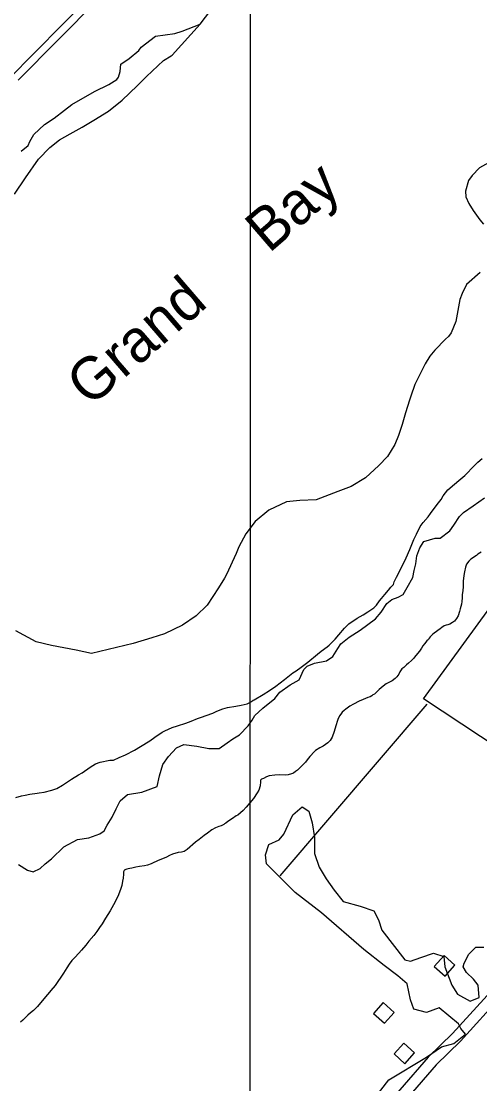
# Model space of a CAD drawing. Extents: x 3263578 to 3301413, y 764927 to 798602.
# Drawn here: x 3274964 to 3276220, y 776528 to 779438 of the extents above; entities that cross this region are included whole.
import ezdxf

# ---------------------------------------------------------------- set-up
doc = ezdxf.new("R2010")
doc.units = 0
for name, color, linetype in [('V-BLDG-OTLN', 7, 'Continuous'), ('V-GRID-MAJR', 7, 'Continuous'), ('V-RIVR-IDEN', 7, 'Continuous'), ('V-ROAD-CNTR', 7, 'Continuous'), ('V-SITE-VEGE', 7, 'Continuous'), ('V-TOPO-SHOR', 7, 'Continuous')]:
    doc.layers.add(name, color=color, linetype=linetype)

msp = doc.modelspace()

# ---------------------------------------------------------------- linework, layer by layer
at = {"layer": 'V-BLDG-OTLN'}
for points in [[(3276125.3, 776822.8), (3276151.9, 776852.7), (3276122.1, 776879.3), (3276095.4, 776849.5)], [(3275958.7, 776693.9), (3275985.3, 776723.7), (3275955.5, 776750.4), (3275928.8, 776720.5)], [(3276014.8, 776583.3), (3276041.5, 776613.1), (3276011.6, 776639.8), (3275985, 776609.9)]]:
    msp.add_lwpolyline(points, close=True, dxfattribs=at)
at = {"layer": 'V-GRID-MAJR'}
msp.add_spline([(3275591.3, 775830), (3275592.2, 781889.4), (3275593.1, 787951.5), (3275593.9, 794013.5), (3275593.9, 794016.1)], degree=3, dxfattribs=at)
at = {"layer": 'V-ROAD-CNTR'}
for points in [[(3274955.7, 779276.4), (3275392.6, 779717.5), (3275797.9, 780131.6), (3276038.2, 780379.7)], [(3277194.8, 777970.7), (3277056, 777784.8), (3276935.6, 777620.8), (3276845.7, 777486), (3276773.8, 777392.2), (3276625.5, 777218), (3276480.6, 777046.5), (3276328.4, 776869.2), (3276259.2, 776790.9), (3276145.3, 776665.7), (3276078.7, 776600.9), (3276001.2, 776511.3), (3275907.5, 776403.5), (3275821.9, 776296.9), (3275728.7, 776181.5), (3275680.8, 776116.1), (3275632.5, 776068.6), (3275515.4, 775977.6), (3275428.3, 775913), (3275327.1, 775831.8)], [(3277218.8, 777952.7), (3277080.1, 777766.9), (3276960.2, 777603.6), (3276870.1, 777468.6), (3276797.2, 777373.4), (3276648.4, 777198.6), (3276503.4, 777027.1), (3276351, 776849.5), (3276281.5, 776770.9), (3276166.9, 776644.8), (3276100.5, 776580.2), (3276023.8, 776491.6), (3275930.5, 776384.3), (3275845.3, 776278.1), (3275752.5, 776163.2), (3275703.5, 776096.4), (3275652.3, 776046), (3275533.6, 775953.7), (3275446.6, 775889.2), (3275376.6, 775833.1)]]:
    msp.add_lwpolyline(points, dxfattribs=at)
at = {"layer": 'V-SITE-VEGE'}
for p, q in [((3275683, 777211.9), (3275708, 777265.1)), ((3275708, 777265.1), (3275733.1, 777287)), ((3275733.1, 777287), (3275751.8, 777274.5)), ((3275751.8, 777274.5), (3275761.2, 777243.2)), ((3275761.2, 777243.2), (3275767.5, 777202.5)), ((3275670.5, 777196.2), (3275683, 777211.9)), ((3275767.5, 777202.5), (3275767.5, 777158.7)), ((3275632.9, 777155.5), (3275642.3, 777183.7)), ((3275642.3, 777183.7), (3275670.5, 777196.2)), ((3275636, 777130.5), (3275632.9, 777155.5)), ((3275767.5, 777158.7), (3275780, 777121.1)), ((3275714.3, 777052.2), (3275636, 777130.5)), ((3275780, 777121.1), (3275798.8, 777089.8)), ((3275798.8, 777089.8), (3275820.7, 777058.5)), ((3275820.7, 777058.5), (3275845.7, 777027.2)), ((3275786.3, 776995.9), (3275714.3, 777052.2)), ((3275845.7, 777027.2), (3275892.6, 777014.7)), ((3275892.6, 777014.7), (3275930.2, 777002.1)), ((3275930.2, 777002.1), (3275942.7, 776977.1)), ((3275902, 776895.7), (3275786.3, 776995.9)), ((3275942.7, 776977.1), (3275952.1, 776948.9)), ((3275952.1, 776948.9), (3276014.7, 776867.5)), ((3275958.4, 776851.9), (3275902, 776895.7)), ((3276058.5, 776873.8), (3276092.9, 776886.3)), ((3276092.9, 776886.3), (3276121.1, 776876.9)), ((3276177.4, 776858.1), (3276189.9, 776883.2)), ((3276189.9, 776883.2), (3276208.7, 776901.9)), ((3276208.7, 776901.9), (3276230.6, 776901.9)), ((3276014.7, 776867.5), (3276030.3, 776864.4)), ((3276030.3, 776864.4), (3276058.5, 776873.8)), ((3276121.1, 776876.9), (3276124.2, 776848.7)), ((3276174.3, 776848.7), (3276177.4, 776858.1)), ((3275995.9, 776823.7), (3275958.4, 776851.9)), ((3276020.9, 776801.8), (3275995.9, 776823.7)), ((3276124.2, 776848.7), (3276143, 776798.6)), ((3276183.7, 776833.1), (3276174.3, 776848.7)), ((3276202.4, 776814.3), (3276183.7, 776833.1)), ((3276030.3, 776757.9), (3276020.9, 776801.8)), ((3276143, 776798.6), (3276158.6, 776773.6)), ((3276215, 776798.6), (3276202.4, 776814.3)), ((3276218.1, 776764.2), (3276215, 776798.6)), ((3276158.6, 776773.6), (3276193.1, 776754.8)), ((3276039.7, 776732.9), (3276030.3, 776757.9)), ((3276108.6, 776736), (3276074.1, 776723.5)), ((3276161.8, 776692.2), (3276108.6, 776736)), ((3276193.1, 776754.8), (3276218.1, 776764.2)), ((3276074.1, 776723.5), (3276039.7, 776732.9)), ((3276168, 776679.7), (3276161.8, 776692.2)), ((3276180.5, 776664), (3276168, 776679.7)), ((3276149.2, 776639), (3276180.5, 776664)), ((3276074.1, 776601.4), (3276114.8, 776629.6)), ((3276114.8, 776629.6), (3276149.2, 776639)), ((3275970.9, 776538.8), (3276074.1, 776601.4)), ((3275870.7, 776410.4), (3275970.9, 776538.8))]:
    msp.add_line(p, q, dxfattribs=at)
for points in [[(3275429.3, 777521.1), (3275447.1, 777528.9), (3275457.9, 777532.4), (3275470.8, 777536.5), (3275489.1, 777543.2), (3275499.9, 777548.4), (3275516, 777555.1), (3275528.9, 777558.2), (3275551.5, 777562.1), (3275566.5, 777564.6), (3275582.6, 777568.6), (3275586.4, 777570.2), (3275594.5, 777575.4), (3275598.9, 777578.6), (3275602.1, 777579.6), (3275626.4, 777594.2), (3275643.7, 777605.2), (3275661, 777616.7), (3275684.9, 777635.1), (3275708.2, 777653.5), (3275716.8, 777659.3), (3275730.9, 777669.3), (3275748.8, 777682.9), (3275775.9, 777704.5), (3275785.6, 777712.4), (3275801.9, 777725), (3275807.8, 777729.7), (3275823.6, 777745.5), (3275833.9, 777757.2), (3275849.8, 777775.7), (3275861.7, 777787.3), (3275883.9, 777803), (3275900.6, 777812.4), (3275913.6, 777820.3), (3275929.8, 777831.3), (3275937.5, 777839.2), (3275945.1, 777850.9), (3275950.6, 777857.2), (3275959.8, 777868.3), (3275970.2, 777879.9), (3275976.7, 777887.9), (3275980, 777891.6), (3275983.3, 777895.8), (3275985.5, 777902.7), (3275991.6, 777915.5), (3276013.7, 777958), (3276018.1, 777968.7), (3276028.1, 777991), (3276039.7, 778018.2), (3276046.9, 778033.6), (3276056.9, 778053.8), (3276065.1, 778065.5), (3276078.1, 778080.8), (3276084.7, 778089.8), (3276103.3, 778114.2), (3276113.7, 778128.5), (3276119.7, 778138), (3276125.7, 778146.5), (3276132.3, 778155), (3276150.2, 778170.2), (3276162.1, 778180.2), (3276178.9, 778193.9), (3276188.1, 778202.9), (3276196.3, 778211.9), (3276207.2, 778223.5), (3276214.8, 778230.3), (3276226.2, 778240.3)], [(3276223.5, 777983.8), (3276214.8, 777978.1), (3276210.5, 777974.9), (3276195.3, 777964.4), (3276189.9, 777959.2), (3276183.3, 777950.7), (3276180.5, 777943.2), (3276177.7, 777929.9), (3276175.9, 777919.7), (3276174.6, 777904.2), (3276174.4, 777889.2), (3276173.2, 777879.1), (3276171.9, 777866.8), (3276171.8, 777859.3), (3276171.1, 777848.6), (3276169.4, 777841.1), (3276166, 777828.8), (3276164.3, 777821.4), (3276160.4, 777809.6), (3276156.5, 777802.7), (3276150.5, 777795.3), (3276145.6, 777791.7), (3276138.1, 777786.9), (3276132.1, 777784.9), (3276127.8, 777783.9), (3276125.1, 777782.9), (3276121.9, 777781.8), (3276116, 777777.6), (3276111.1, 777774), (3276105.1, 777769.8), (3276101.3, 777766.6), (3276095.4, 777761.9), (3276090.5, 777758.7), (3276088.9, 777757.1), (3276084, 777751.9), (3276081.2, 777748.2), (3276079.1, 777744.4), (3276074.7, 777740.8), (3276068.7, 777733.3), (3276064.3, 777727), (3276060.5, 777721.1), (3276054.5, 777712.7), (3276049.6, 777706.3), (3276041.4, 777696.8), (3276039.2, 777693.6), (3276032.7, 777687.3), (3276024.5, 777679.9), (3276019.6, 777675.2), (3276012, 777668.3), (3276006.6, 777664.1), (3276001.2, 777656.1), (3275997.9, 777650.3), (3275992.9, 777642.3), (3275988.6, 777637.6), (3275980.4, 777631.3), (3275976.1, 777629.7), (3275963.2, 777623), (3275955.1, 777617.2), (3275944.7, 777608.2), (3275931.2, 777595.1), (3275927.4, 777593), (3275924.7, 777590.9), (3275919.8, 777587.7), (3275913.3, 777585.7), (3275900.4, 777580.5), (3275889.6, 777575.9), (3275874, 777568.1), (3275864.3, 777562.3), (3275853.4, 777554.4), (3275848.6, 777550.2), (3275842.6, 777546), (3275839.3, 777540.2), (3275836, 777535.9), (3275831.1, 777525.8), (3275829.9, 777522.6), (3275826, 777508.2), (3275821.5, 777492.8), (3275815.9, 777477.3), (3275810.4, 777468.3), (3275803.9, 777461.4), (3275791.4, 777453.1), (3275782.2, 777448.4), (3275770.3, 777440.5), (3275764.4, 777435.8), (3275757.3, 777427.3), (3275754.6, 777424.7), (3275747.5, 777415.1), (3275742.6, 777408.8)], [(3274949.5, 777311.8), (3274964.6, 777316.4), (3274975.3, 777318.9), (3274987.7, 777321.4), (3275007.6, 777324.3), (3275012.9, 777324.8), (3275026.9, 777326.7), (3275048.4, 777332.3), (3275061.3, 777336.4), (3275077, 777345.8), (3275101.9, 777362.6), (3275121.3, 777374.1), (3275131, 777379.3), (3275153.2, 777395.6), (3275167.8, 777403.9), (3275180.7, 777408.5), (3275207.1, 777414), (3275217.2, 777414.4), (3275232.3, 777421.7), (3275249.6, 777428.9), (3275274.4, 777442), (3275291.2, 777451.4), (3275316, 777467.1), (3275330.1, 777477), (3275350.1, 777490.7), (3275357.1, 777494.3), (3275377.6, 777503.6), (3275392.2, 777508.2), (3275415.3, 777515.4), (3275429.3, 777521.1)], [(3275742.6, 777408.8), (3275733.9, 777399.8), (3275720.8, 777387.2), (3275715.4, 777383), (3275709.4, 777378.8), (3275704.6, 777377.2), (3275695.4, 777374.1), (3275686.9, 777373.7), (3275670.3, 777374), (3275658.5, 777373.6), (3275642.9, 777371.2), (3275635.9, 777368.6), (3275627.3, 777364.4), (3275622.4, 777362.4), (3275619.7, 777359.2), (3275619.1, 777355.5), (3275618.9, 777343.7), (3275615, 777332.5), (3275610.1, 777324.5), (3275600.2, 777309.1), (3275580.6, 777285.9), (3275571.9, 777276.4), (3275557.8, 777264.2), (3275552.9, 777261.6), (3275543.2, 777254.8), (3275530.2, 777246.4), (3275524.2, 777241.7), (3275521, 777239.6), (3275518.8, 777238.6), (3275515.1, 777236), (3275511.8, 777234.4), (3275505.4, 777232.3), (3275496.2, 777228.7), (3275486.5, 777223.5), (3275474.6, 777214.6), (3275465.4, 777208.3), (3275451.3, 777197.3), (3275441.5, 777189.4), (3275418.7, 777169.9), (3275410.1, 777164.7), (3275403.1, 777162.6), (3275394, 777161.2), (3275378.9, 777156.6), (3275369.8, 777152.9), (3275361.7, 777148.8), (3275350.9, 777144.1), (3275343.9, 777141.6), (3275337.4, 777139), (3275323.9, 777132.2), (3275320.1, 777130.1), (3275309.9, 777126.5), (3275301.9, 777125), (3275287.9, 777123.1), (3275278.2, 777121.6), (3275267, 777119.1), (3275261.6, 777118.1), (3275256.7, 777116.6), (3275253, 777115.6), (3275250.3, 777115.1), (3275248.1, 777114), (3275247, 777112.5), (3275246, 777112.5), (3275244.3, 777108.7), (3275244.2, 777102.3), (3275243, 777091.1), (3275241.8, 777083.1), (3275239.5, 777071.3), (3275237.2, 777063.3), (3275230.5, 777045.2), (3275223.9, 777031.9), (3275217.3, 777018.1), (3275207.9, 777002.2), (3275195.3, 776982), (3275186, 776966.1), (3275178.8, 776956), (3275171.7, 776944.9), (3275163.5, 776934.3), (3275149.4, 776918.4), (3275141.2, 776907.8), (3275129.2, 776894.1), (3275122.1, 776886.1), (3275110.7, 776874), (3275102.5, 776865.6), (3275095.4, 776855.5), (3275088.8, 776845.9), (3275080.1, 776831.1), (3275057.1, 776797.7), (3275045.1, 776783.9), (3275041.8, 776779.2), (3275030.9, 776766.5), (3275009.1, 776740), (3274997.7, 776728.9), (3274989.5, 776722.1), (3274982.5, 776715.8), (3274968.4, 776702), (3274961.8, 776696.8)]]:
    msp.add_lwpolyline(points, dxfattribs=at)
at = {"layer": 'V-TOPO-SHOR'}
for p, q in [((3274928.5, 779278.1), (3275184.5, 779538.4)), ((3276075.3, 777567.7), (3275672.7, 777098.1))]:
    msp.add_line(p, q, dxfattribs=at)
for points in [[(3274946, 778964.2), (3274975.6, 779008.5), (3275011.4, 779059.8), (3275042.6, 779091.8), (3275069.3, 779113.3), (3275098.5, 779129.6), (3275131.2, 779147.5), (3275163.1, 779167.2), (3275202.9, 779191.2), (3275240.2, 779221.3), (3275282, 779261.1), (3275307, 779286.1), (3275354.1, 779330.2), (3275374.5, 779343), (3275377.2, 779344.7), (3275453.9, 779429.6), (3275640, 779675.1)], [(3274963.8, 779081.6), (3274983.6, 779097.1), (3274988, 779108.1), (3274999.1, 779128), (3275027.8, 779154.5), (3275054.2, 779172.1), (3275082.9, 779194.2), (3275102.8, 779209.6), (3275164.6, 779244.9), (3275204.3, 779264.8), (3275226.4, 779278), (3275230.8, 779284.7), (3275235.2, 779300.1), (3275237.4, 779320), (3275259.5, 779335.4), (3275286, 779357.5), (3275292.6, 779366.3), (3275332.3, 779397.2), (3275385.3, 779403.8), (3275405.2, 779410.4), (3275453.9, 779429.6)], [(3276253.8, 779055.3), (3276219.3, 779036.5), (3276198.8, 779014.9), (3276188.9, 779001.9), (3276180.6, 778972.2), (3276182.1, 778957.2), (3276189.7, 778938.7), (3276201.7, 778919.2), (3276219.8, 778893.5), (3276230.1, 778881.9)], [(3276221.1, 778749.6), (3276183.8, 778716.8)], [(3276183.8, 778716.8), (3276172, 778692.4), (3276165.6, 778675.8), (3276158, 778635.6), (3276154.2, 778615.4), (3276141.5, 778584.1), (3276134.3, 778574.5), (3276126.3, 778566.7), (3276096.9, 778537.3), (3276083.5, 778520.9), (3276070, 778500), (3276051.9, 778463.4), (3276042, 778443.4), (3276031, 778411.1), (3276027.3, 778399.7), (3276016.2, 778365.7), (3276007, 778333.4), (3275996.9, 778303.7), (3275987.7, 778278.4), (3275967.1, 778246.2), (3275943.9, 778221.1), (3275906.5, 778187.5), (3275867.6, 778163.5), (3275831.4, 778150), (3275771.4, 778127.2), (3275727.5, 778125.2), (3275690.6, 778121.4), (3275642, 778099.3), (3275604.7, 778068.2), (3275579.6, 778034.4), (3275559.8, 777998.7), (3275552.5, 777980.4), (3275526.2, 777922.9), (3275520.8, 777912.4), (3275504.6, 777886.4), (3275473.2, 777838.6), (3275442.9, 777809.2), (3275405.7, 777784.3), (3275356.2, 777760.5), (3275321.8, 777749.6), (3275270.7, 777733.7), (3275157.1, 777706.4), (3275115.1, 777715.8), (3275046.9, 777728.2), (3275004.9, 777738.5), (3274949.2, 777768.3)], [(3274957, 777128.5), (3274981.2, 777113.1), (3274996.7, 777108.7), (3275016.5, 777117.5), (3275029.8, 777130.7), (3275047.4, 777144), (3275080.5, 777177.1), (3275118.1, 777196.9), (3275149, 777201.4), (3275179.9, 777212.4), (3275190.9, 777221.2), (3275199.7, 777236.7), (3275213, 777258.7), (3275224, 777280.8), (3275235, 777302.9), (3275254.9, 777320.5), (3275294.6, 777327.1), (3275336.6, 777342.6), (3275343.2, 777371.3), (3275352, 777402.2), (3275367.5, 777424.2), (3275389.5, 777448.5), (3275409.4, 777457.3), (3275444.7, 777452.9), (3275477.8, 777446.3), (3275506.5, 777446.3), (3275528.6, 777461.7), (3275544, 777472.8), (3275561.7, 777483.8), (3275586, 777508.1), (3275597, 777523.5), (3275603.6, 777536.8), (3275625.7, 777556.6), (3275658.8, 777583.1), (3275672, 777600.8), (3275700.7, 777620.6), (3275725, 777633.9), (3275738.2, 777662.5), (3275747.1, 777671.4), (3275766.9, 777680.2), (3275800, 777686.8), (3275817.7, 777697.8), (3275830.9, 777719.9), (3275839.8, 777733.2), (3275861.8, 777750.8), (3275892.7, 777770.7), (3275934.7, 777801.6), (3275950.1, 777819.2), (3275965.6, 777843.5), (3275978.8, 777854.5), (3275996.5, 777861.1), (3276009.7, 777867.8), (3276020.7, 777887.6), (3276036.2, 777914.1), (3276040.6, 777934), (3276045, 777951.6), (3276047.2, 777973.7), (3276056.1, 777995.8), (3276067.1, 778013.4), (3276098, 778022.2), (3276111.2, 778022.2), (3276137.7, 778042.1), (3276148.8, 778057.5), (3276164.2, 778081.8), (3276175.2, 778092.8), (3276201.7, 778110.5), (3276232.6, 778132.6)], [(3276588, 777237), (3276065.7, 777582.1), (3276247.8, 777831.3)]]:
    msp.add_lwpolyline(points, dxfattribs=at)

# ---------------------------------------------------------------- texts
at = {"layer": 'V-RIVR-IDEN'}
msp.add_text('Grand     Bay', height=116, rotation=40.7276, dxfattribs=at).set_placement((3275152.4, 778378.7))

doc.saveas('drawing.dxf')
